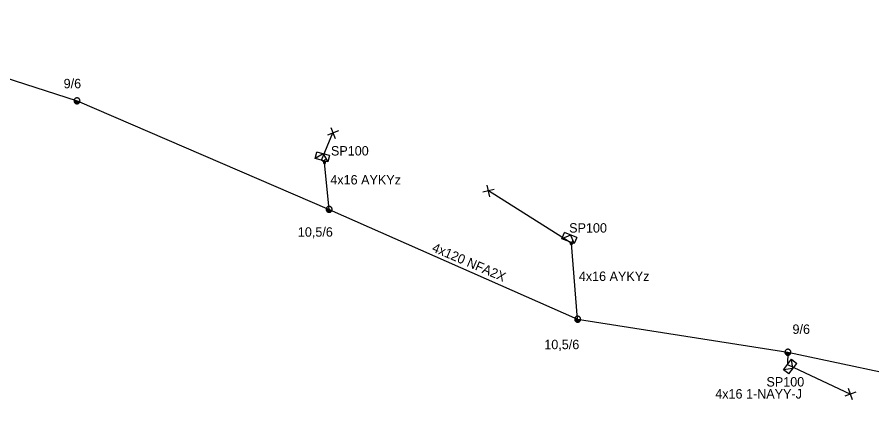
# Model space of a CAD drawing. Extents: x -788458 to -786145, y -1154772 to -1152372.
# Drawn here: x -786360.6 to -786269.7, y -1153533.3 to -1153491 of the extents above; entities that cross this region are included whole.
import ezdxf

# ---------------------------------------------------------------- set-up
doc = ezdxf.new("R2010")
doc.units = 0
for name, color, linetype in [('Vrstva 1', 7, 'Continuous'), ('Vrstva 12', 7, 'Continuous'), ('Vrstva 13', 7, 'Continuous'), ('Vrstva 2', 7, 'Continuous'), ('Vrstva 31', 7, 'Continuous'), ('Vrstva 33', 7, 'Continuous'), ('Vrstva 34', 7, 'Continuous'), ('Vrstva 50', 7, 'Continuous'), ('Vrstva 51', 7, 'Continuous'), ('Vrstva 52', 7, 'Continuous'), ('Vrstva 54', 7, 'Continuous'), ('Vrstva 55', 7, 'Continuous'), ('Vrstva 59', 7, 'Continuous'), ('Vrstva 9', 7, 'Continuous')]:
    doc.layers.add(name, color=color, linetype=linetype)

# ---------------------------------------------------------------- blocks, each defined once
blk = doc.blocks.new('NN440')
at = {"layer": 'Vrstva 2'}
for points in [[(0.63, 0), (0.63, 0.06), (0.62, 0.13), (0.6, 0.19), (0.58, 0.25), (0.55, 0.31), (0.51, 0.37), (0.47, 0.42), (0.42, 0.46), (0.37, 0.51), (0.32, 0.54), (0.26, 0.57), (0.2, 0.59), (0.13, 0.61), (0.07, 0.62), (0, 0.63), (-0.06, 0.62), (-0.13, 0.61), (-0.19, 0.59), (-0.26, 0.57), (-0.31, 0.54), (-0.37, 0.51), (-0.42, 0.46), (-0.47, 0.42), (-0.51, 0.37), (-0.54, 0.31), (-0.57, 0.25), (-0.6, 0.19), (-0.62, 0.13), (-0.63, 0.06), (-0.63, 0), (-0.63, -0.07), (-0.62, -0.14), (-0.6, -0.2), (-0.57, -0.26), (-0.54, -0.32), (-0.51, -0.37), (-0.47, -0.43), (-0.42, -0.47), (-0.37, -0.51), (-0.31, -0.55), (-0.26, -0.58), (-0.19, -0.6), (-0.13, -0.62), (-0.06, -0.63), (0, -0.63), (0.07, -0.63), (0.13, -0.62), (0.2, -0.6), (0.26, -0.58), (0.32, -0.55), (0.37, -0.51), (0.42, -0.47), (0.47, -0.43), (0.51, -0.37), (0.55, -0.32), (0.58, -0.26), (0.6, -0.2), (0.62, -0.14), (0.63, -0.07), (0.63, 0)], [(-0.63, 0), (0.63, 0)], [(-0.6, -0.18), (0.57, -0.18)], [(-0.51, -0.32), (0.5, -0.32)], [(-0.37, -0.47), (0.35, -0.47)]]:
    blk.add_lwpolyline(points, dxfattribs=at)
blk = doc.blocks.new('NN800')
at = {"layer": 'Vrstva 1'}
for points in [[(-0.442, 0.442), (0.442, -0.442)], [(-0.442, -0.442), (0.442, 0.442)]]:
    blk.add_lwpolyline(points, dxfattribs=at)
blk = doc.blocks.new('NN630')
at = {"layer": 'Vrstva 9'}
for points in [[(-0.003, -0.7), (-0.703, 0)], [(-0.703, -0.7), (-0.703, 0), (0.697, 0), (0.697, -0.7)], [(-0.703, -0.7), (0.697, -0.7)], [(-0.003, -0.7), (0.697, 0)]]:
    blk.add_lwpolyline(points, dxfattribs=at)
blk = doc.blocks.new('NN500')
at = {"layer": 'Vrstva 2'}
for points in [[(0, -0.24), (0.02, -0.23), (0.05, -0.23), (0.07, -0.22), (0.09, -0.22), (0.12, -0.2), (0.14, -0.19), (0.16, -0.18), (0.17, -0.16), (0.19, -0.14), (0.2, -0.12), (0.21, -0.1), (0.22, -0.07), (0.23, -0.05), (0.23, -0.02), (0.23, 0), (0.23, 0.02), (0.23, 0.05), (0.22, 0.07), (0.21, 0.1), (0.2, 0.12), (0.19, 0.14), (0.17, 0.16), (0.16, 0.17), (0.14, 0.19), (0.12, 0.2), (0.09, 0.21), (0.07, 0.22), (0.05, 0.23), (0.02, 0.23), (0, 0.23), (-0.03, 0.23), (-0.05, 0.23), (-0.07, 0.22), (-0.1, 0.21), (-0.12, 0.2), (-0.14, 0.19), (-0.16, 0.17), (-0.18, 0.16), (-0.19, 0.14), (-0.2, 0.12), (-0.22, 0.1), (-0.22, 0.07), (-0.23, 0.05), (-0.23, 0.02), (-0.24, 0), (-0.23, -0.02), (-0.23, -0.05), (-0.22, -0.07), (-0.22, -0.1), (-0.2, -0.12), (-0.19, -0.14), (-0.18, -0.16), (-0.16, -0.18), (-0.14, -0.19), (-0.12, -0.2), (-0.1, -0.22), (-0.07, -0.22), (-0.05, -0.23), (-0.03, -0.23), (0, -0.24)], [(0, -0.24), (0.02, -0.23), (0.05, -0.23), (0.07, -0.22), (0.09, -0.22), (0.12, -0.2), (0.14, -0.19), (0.16, -0.18), (0.17, -0.16), (0.19, -0.14), (0.2, -0.12), (0.21, -0.1), (0.22, -0.07), (0.23, -0.05), (0.23, -0.02), (0.23, 0), (0.23, 0.02), (0.23, 0.05), (0.22, 0.07), (0.21, 0.1), (0.2, 0.12), (0.19, 0.14), (0.17, 0.16), (0.16, 0.17), (0.14, 0.19), (0.12, 0.2), (0.09, 0.21), (0.07, 0.22), (0.05, 0.23), (0.02, 0.23), (0, 0.23), (-0.03, 0.23), (-0.05, 0.23), (-0.07, 0.22), (-0.1, 0.21), (-0.12, 0.2), (-0.14, 0.19), (-0.16, 0.17), (-0.18, 0.16), (-0.19, 0.14), (-0.2, 0.12), (-0.22, 0.1), (-0.22, 0.07), (-0.23, 0.05), (-0.23, 0.02), (-0.24, 0), (-0.23, -0.02), (-0.23, -0.05), (-0.22, -0.07), (-0.22, -0.1), (-0.2, -0.12), (-0.19, -0.14), (-0.18, -0.16), (-0.16, -0.18), (-0.14, -0.19), (-0.12, -0.2), (-0.1, -0.22), (-0.07, -0.22), (-0.05, -0.23), (-0.03, -0.23), (0, -0.24)], [(0, -0.21), (0.02, -0.2), (0.04, -0.2), (0.06, -0.2), (0.08, -0.19), (0.1, -0.18), (0.12, -0.17), (0.14, -0.15), (0.15, -0.14), (0.16, -0.12), (0.18, -0.1), (0.19, -0.08), (0.19, -0.06), (0.2, -0.04), (0.2, -0.02), (0.2, 0), (0.2, 0.02), (0.2, 0.04), (0.19, 0.06), (0.19, 0.08), (0.18, 0.1), (0.16, 0.12), (0.15, 0.14), (0.14, 0.15), (0.12, 0.17), (0.1, 0.18), (0.08, 0.19), (0.06, 0.19), (0.04, 0.2), (0.02, 0.2), (0, 0.2), (-0.02, 0.2), (-0.04, 0.2), (-0.06, 0.19), (-0.08, 0.19), (-0.1, 0.18), (-0.12, 0.17), (-0.14, 0.15), (-0.15, 0.14), (-0.17, 0.12), (-0.18, 0.1), (-0.19, 0.08), (-0.2, 0.06), (-0.2, 0.04), (-0.21, 0.02), (-0.21, 0), (-0.21, -0.02), (-0.2, -0.04), (-0.2, -0.06), (-0.19, -0.08), (-0.18, -0.1), (-0.17, -0.12), (-0.15, -0.14), (-0.14, -0.15), (-0.12, -0.17), (-0.1, -0.18), (-0.08, -0.19), (-0.06, -0.2), (-0.04, -0.2), (-0.02, -0.2), (0, -0.21)], [(0, -0.18), (0.02, -0.18), (0.04, -0.17), (0.05, -0.17), (0.07, -0.16), (0.09, -0.15), (0.1, -0.14), (0.12, -0.13), (0.13, -0.12), (0.14, -0.1), (0.15, -0.09), (0.16, -0.07), (0.17, -0.05), (0.17, -0.04), (0.17, -0.02), (0.17, 0), (0.17, 0.02), (0.17, 0.04), (0.17, 0.05), (0.16, 0.07), (0.15, 0.09), (0.14, 0.1), (0.13, 0.12), (0.12, 0.13), (0.1, 0.14), (0.09, 0.15), (0.07, 0.16), (0.05, 0.17), (0.04, 0.17), (0.02, 0.17), (0, 0.18), (-0.02, 0.17), (-0.04, 0.17), (-0.06, 0.17), (-0.07, 0.16), (-0.09, 0.15), (-0.1, 0.14), (-0.12, 0.13), (-0.13, 0.12), (-0.14, 0.1), (-0.15, 0.09), (-0.16, 0.07), (-0.17, 0.05), (-0.17, 0.04), (-0.18, 0.02), (-0.18, 0), (-0.18, -0.02), (-0.17, -0.04), (-0.17, -0.05), (-0.16, -0.07), (-0.15, -0.09), (-0.14, -0.1), (-0.13, -0.12), (-0.12, -0.13), (-0.1, -0.14), (-0.09, -0.15), (-0.07, -0.16), (-0.06, -0.17), (-0.04, -0.17), (-0.02, -0.18), (0, -0.18)], [(0, -0.15), (0.01, -0.15), (0.03, -0.14), (0.04, -0.14), (0.06, -0.13), (0.07, -0.13), (0.08, -0.12), (0.1, -0.11), (0.11, -0.1), (0.12, -0.09), (0.13, -0.07), (0.13, -0.06), (0.14, -0.05), (0.14, -0.03), (0.14, -0.02), (0.14, 0), (0.14, 0.01), (0.14, 0.03), (0.14, 0.04), (0.13, 0.06), (0.13, 0.07), (0.12, 0.09), (0.11, 0.1), (0.1, 0.11), (0.08, 0.12), (0.07, 0.13), (0.06, 0.13), (0.04, 0.14), (0.03, 0.14), (0.01, 0.14), (0, 0.15), (-0.02, 0.14), (-0.03, 0.14), (-0.05, 0.14), (-0.06, 0.13), (-0.07, 0.13), (-0.09, 0.12), (-0.1, 0.11), (-0.11, 0.1), (-0.12, 0.09), (-0.13, 0.07), (-0.13, 0.06), (-0.14, 0.04), (-0.14, 0.03), (-0.15, 0.01), (-0.15, 0), (-0.15, -0.02), (-0.14, -0.03), (-0.14, -0.05), (-0.13, -0.06), (-0.13, -0.07), (-0.12, -0.09), (-0.11, -0.1), (-0.1, -0.11), (-0.09, -0.12), (-0.07, -0.13), (-0.06, -0.13), (-0.05, -0.14), (-0.03, -0.14), (-0.02, -0.15), (0, -0.15)], [(0, -0.12), (0.01, -0.12), (0.02, -0.11), (0.03, -0.11), (0.05, -0.11), (0.06, -0.1), (0.07, -0.09), (0.08, -0.09), (0.09, -0.08), (0.09, -0.07), (0.1, -0.06), (0.11, -0.05), (0.11, -0.04), (0.11, -0.02), (0.11, -0.01), (0.12, 0), (0.11, 0.01), (0.11, 0.02), (0.11, 0.04), (0.11, 0.05), (0.1, 0.06), (0.09, 0.07), (0.09, 0.08), (0.08, 0.09), (0.07, 0.09), (0.06, 0.1), (0.05, 0.11), (0.03, 0.11), (0.02, 0.11), (0.01, 0.12), (0, 0.12), (-0.01, 0.12), (-0.03, 0.11), (-0.04, 0.11), (-0.05, 0.11), (-0.06, 0.1), (-0.07, 0.09), (-0.08, 0.09), (-0.09, 0.08), (-0.1, 0.07), (-0.1, 0.06), (-0.11, 0.05), (-0.11, 0.04), (-0.12, 0.02), (-0.12, 0.01), (-0.12, 0), (-0.12, -0.01), (-0.12, -0.02), (-0.11, -0.04), (-0.11, -0.05), (-0.1, -0.06), (-0.1, -0.07), (-0.09, -0.08), (-0.08, -0.09), (-0.07, -0.09), (-0.06, -0.1), (-0.05, -0.11), (-0.04, -0.11), (-0.03, -0.11), (-0.01, -0.12), (0, -0.12)], [(0, -0.09), (0.01, -0.09), (0.02, -0.09), (0.03, -0.08), (0.03, -0.08), (0.04, -0.08), (0.05, -0.07), (0.06, -0.07), (0.06, -0.06), (0.07, -0.05), (0.07, -0.04), (0.08, -0.04), (0.08, -0.03), (0.08, -0.02), (0.09, -0.01), (0.09, 0), (0.09, 0.01), (0.08, 0.02), (0.08, 0.03), (0.08, 0.03), (0.07, 0.04), (0.07, 0.05), (0.06, 0.06), (0.06, 0.06), (0.05, 0.07), (0.04, 0.07), (0.03, 0.08), (0.03, 0.08), (0.02, 0.08), (0.01, 0.09), (0, 0.09), (-0.01, 0.09), (-0.02, 0.08), (-0.03, 0.08), (-0.04, 0.08), (-0.04, 0.07), (-0.05, 0.07), (-0.06, 0.06), (-0.07, 0.06), (-0.07, 0.05), (-0.08, 0.04), (-0.08, 0.03), (-0.08, 0.03), (-0.09, 0.02), (-0.09, 0.01), (-0.09, 0), (-0.09, -0.01), (-0.09, -0.02), (-0.08, -0.03), (-0.08, -0.04), (-0.08, -0.04), (-0.07, -0.05), (-0.07, -0.06), (-0.06, -0.07), (-0.05, -0.07), (-0.04, -0.08), (-0.04, -0.08), (-0.03, -0.08), (-0.02, -0.09), (-0.01, -0.09), (0, -0.09)], [(0, -0.06), (0, -0.06), (0.01, -0.06), (0.02, -0.05), (0.02, -0.05), (0.03, -0.05), (0.03, -0.05), (0.04, -0.04), (0.04, -0.04), (0.05, -0.03), (0.05, -0.03), (0.05, -0.02), (0.05, -0.02), (0.05, -0.01), (0.06, -0.01), (0.06, 0), (0.06, 0.01), (0.05, 0.01), (0.05, 0.02), (0.05, 0.02), (0.05, 0.03), (0.05, 0.03), (0.04, 0.04), (0.04, 0.04), (0.03, 0.05), (0.03, 0.05), (0.02, 0.05), (0.02, 0.05), (0.01, 0.06), (0, 0.06), (0, 0.06), (-0.01, 0.06), (-0.01, 0.06), (-0.02, 0.05), (-0.02, 0.05), (-0.03, 0.05), (-0.03, 0.05), (-0.04, 0.04), (-0.04, 0.04), (-0.05, 0.03), (-0.05, 0.03), (-0.05, 0.02), (-0.06, 0.02), (-0.06, 0.01), (-0.06, 0.01), (-0.06, 0), (-0.06, -0.01), (-0.06, -0.01), (-0.06, -0.02), (-0.05, -0.02), (-0.05, -0.03), (-0.05, -0.03), (-0.04, -0.04), (-0.04, -0.04), (-0.03, -0.05), (-0.03, -0.05), (-0.02, -0.05), (-0.02, -0.05), (-0.01, -0.06), (-0.01, -0.06), (0, -0.06)], [(0, -0.03), (0, -0.03), (0, -0.03), (0.01, -0.03), (0.01, -0.03), (0.01, -0.02), (0.02, -0.02), (0.02, -0.02), (0.02, -0.02), (0.02, -0.02), (0.02, -0.01), (0.02, -0.01), (0.03, -0.01), (0.03, -0.01), (0.03, 0), (0.03, 0), (0.03, 0), (0.03, 0.01), (0.03, 0.01), (0.02, 0.01), (0.02, 0.01), (0.02, 0.02), (0.02, 0.02), (0.02, 0.02), (0.02, 0.02), (0.01, 0.02), (0.01, 0.02), (0.01, 0.03), (0, 0.03), (0, 0.03), (0, 0.03), (0, 0.03), (-0.01, 0.03), (-0.01, 0.03), (-0.01, 0.02), (-0.02, 0.02), (-0.02, 0.02), (-0.02, 0.02), (-0.02, 0.02), (-0.02, 0.02), (-0.03, 0.01), (-0.03, 0.01), (-0.03, 0.01), (-0.03, 0.01), (-0.03, 0), (-0.03, 0), (-0.03, 0), (-0.03, -0.01), (-0.03, -0.01), (-0.03, -0.01), (-0.03, -0.01), (-0.02, -0.02), (-0.02, -0.02), (-0.02, -0.02), (-0.02, -0.02), (-0.02, -0.02), (-0.01, -0.03), (-0.01, -0.03), (-0.01, -0.03), (0, -0.03), (0, -0.03)], [(0.23, 0), (0.7, 0)]]:
    blk.add_lwpolyline(points, dxfattribs=at)

msp = doc.modelspace()

# ---------------------------------------------------------------- linework, layer by layer
at = {"layer": 'Vrstva 50'}
msp.add_lwpolyline([(-786381.77, -1153491.026), (-786354.19, -1153499.92), (-786327.4, -1153511.45), (-786300.99, -1153523.12), (-786278.65, -1153526.63), (-786247.26, -1153533.29)], dxfattribs=at)
at = {"layer": 'Vrstva 52'}
msp.add_lwpolyline([(-786278.65, -1153526.63), (-786278.68, -1153527.931)], dxfattribs=at)
at = {"layer": 'Vrstva 54'}
for points in [[(-786327.4, -1153511.45), (-786327.89, -1153506.46), (-786328.223, -1153506.234)], [(-786300.99, -1153523.12), (-786301.66, -1153515.08), (-786302.01, -1153514.83)]]:
    msp.add_lwpolyline(points, dxfattribs=at)
at = {"layer": 'Vrstva 59'}
for points in [[(-786328.223, -1153506.234), (-786326.993, -1153503.334)], [(-786302.01, -1153514.83), (-786310.47, -1153509.498)], [(-786278.68, -1153527.931), (-786272.01, -1153531.091)]]:
    msp.add_lwpolyline(points, dxfattribs=at)

# ---------------------------------------------------------------- block references
at = {"layer": 'Vrstva 13'}
for name, p, xscale, yscale, rotation in [('NN440', (-786354.19, -1153499.92), 0.49999999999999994, 0.5000000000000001, -12.495902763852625), ('NN500', (-786327.89, -1153506.46), 0.5, 0.5, 77.14666036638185), ('NN440', (-786327.4, -1153511.45), 0.5, 0.49999999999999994, -23.28629324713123), ('NN500', (-786301.66, -1153515.08), 0.49999999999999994, 0.5, 65.6781202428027), ('NN440', (-786300.99, -1153523.12), 0.5, 0.5, -23.839584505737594), ('NN440', (-786278.65, -1153526.63), 0.5000000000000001, 0.5, -8.929159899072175)]:
    msp.add_blockref(name, p, dxfattribs=dict(at, xscale=xscale, yscale=yscale, rotation=rotation))
at = {"layer": 'Vrstva 31'}
for p, rotation in [((-786328.223, -1153506.234), 164.5976695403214), ((-786302.01, -1153514.83), 157.8403559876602), ((-786278.68, -1153527.931), 52.04264715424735)]:
    msp.add_blockref('NN630', p, dxfattribs=dict(at, rotation=rotation))
at = {"layer": 'Vrstva 34'}
for p, rotation in [((-786326.993, -1153503.335), -112.98352224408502), ((-786310.469, -1153509.497), 147.86712510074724), ((-786272.01, -1153531.091), 154.65018042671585)]:
    msp.add_blockref('NN800', p, dxfattribs=dict(at, rotation=rotation))

# ---------------------------------------------------------------- texts
at = {"layer": 'Vrstva 12'}
for s, p in [('9/6', (-786355.61, -1153498.589)), ('10,5/6', (-786330.723, -1153514.356)), ('9/6', (-786278.163, -1153524.681)), ('10,5/6', (-786304.536, -1153526.309))]:
    msp.add_text(s, height=1, dxfattribs=at).set_placement(p)
at = {"layer": 'Vrstva 33'}
for p in [(-786327.207, -1153505.731), (-786301.896, -1153513.922), (-786280.931, -1153530.275)]:
    msp.add_text('SP100', height=1, dxfattribs=at).set_placement(p)
at = {"layer": 'Vrstva 51'}
msp.add_text('4x120 NFA2X', height=1, rotation=336.877, dxfattribs=at).set_placement((-786316.552, -1153515.886))
at = {"layer": 'Vrstva 54'}
msp.add_text('4x16 1-NAYY-J', height=1, dxfattribs=at).set_placement((-786286.373, -1153531.554))
at = {"layer": 'Vrstva 55'}
msp.add_text('4x16 AYKYz', height=1, dxfattribs=at).set_placement((-786327.274, -1153508.808))
msp.add_text('4x16 AYKYz', height=1, rotation=359.902, dxfattribs=at).set_placement((-786300.87, -1153519.054))

doc.saveas('drawing.dxf')
